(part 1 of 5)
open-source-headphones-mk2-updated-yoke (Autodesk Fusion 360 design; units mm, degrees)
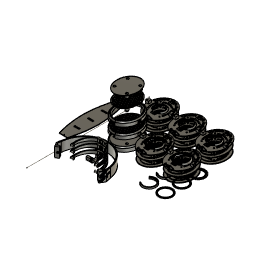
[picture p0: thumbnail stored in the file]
sketch "Pad Mount Start" plane through (0, 0, 0) normal (0, 0, 1) x axis (1, 0, 0)
  curve K1 (0, 53) -> (0, -53)
  curve K2 (-43, 0) -> (43, 0)
  curve K3 (0, 41) -> (0, -41)
  curve K4 (-31, 0) -> (31, 0)
  curve K5 (0, 43) -> (0, -43)
  curve K6 (-33, 0) -> (33, 0)
  line L1 (29.0688, 20.3542) -> (0, 0)
  line L2 (35.4865, 0) -> (0, 0)
  line L3 (20.8361, 33.3448) -> (0, 0)
  line L4 (39.3194, 0) -> (0, 0)
  curve K7 (0, -35.5) -> (0, 35.5)
  curve K8 (25.5, 0) -> (-25.5, 0)
  line L5 (29.0688, -20.3542) -> (0, 0)
  line L6 (20.8361, -33.3448) -> (0, 0)
  line L7 (0, 20) -> (0, 2.5)
  line L8 (-29.0688, -20.3542) -> (0, 0)
  line L9 (-20.8361, -33.3448) -> (0, 0)
  line L10 (-29.0688, 20.3542) -> (0, 0)
  line L11 (-20.8361, 33.3448) -> (0, 0)
  line L12 (37.023, 0) -> (0, 0)
  line L13 (11.725, -5.6147) -> (15.1969, -7.6193)
  line L14 (15.1969, 7.6193) -> (11.725, 5.6147)
  line L15 (1, 10.9545) -> (1, 6.9282)
  line L16 (6.5, -2.5981) -> (9.9868, -4.6112)
  line L17 (10.725, 7.3468) -> (14.1969, 9.3513)
  line L18 (1, 16.9706) -> (1, 12.9615)
  line L19 (11.43, 15.1775) -> (14.6475, 19.0119)
  line L20 (1, 23.9792) -> (1, 18.9737)
  line L21 (-1, 18.9737) -> (-1, 23.9792)
  line L22 (-14.6475, 19.0119) -> (-11.43, 15.1775)
  line L23 (-12.9621, 13.8919) -> (-16.1795, 17.7263)
  line L24 (-23.4412, 5.1487) -> (-18.5118, 4.2796)
  line L25 (-18.8591, 2.3099) -> (-23.7885, 3.1791)
  line L26 (-21.2666, -11.1236) -> (-16.9317, -8.6208)
  line L27 (-15.9317, -10.3529) -> (-20.2666, -12.8556)
  line L28 (-9.141, -22.191) -> (-7.4291, -17.4874)
  line L29 (-5.5497, -18.1714) -> (-7.2617, -22.8751)
  line L30 (7.2617, -22.8751) -> (5.5497, -18.1714)
  line L31 (7.4291, -17.4874) -> (9.141, -22.191)
  line L32 (20.2666, -12.8556) -> (15.9317, -10.3529)
  line L33 (16.9317, -8.6208) -> (21.2666, -11.1236)
  line L34 (23.7885, 3.1791) -> (18.8591, 2.3099)
  line L35 (18.5118, 4.2796) -> (23.4412, 5.1487)
  line L36 (16.1795, 17.7263) -> (12.9621, 13.8919)
  line L37 (-14.1969, 9.3513) -> (-10.725, 7.3468)
  line L38 (-1, 12.9615) -> (-1, 16.9706)
  line L39 (-11.725, 5.6147) -> (-15.1969, 7.6193)
  line L40 (-15.1969, -7.6193) -> (-11.725, -5.6147)
  line L41 (-9.9868, -4.6112) -> (-6.5, -2.5981)
  line L42 (-1, 6.9282) -> (-1, 10.9545)
  line L43 (8.9868, -6.3433) -> (5.5, -4.3301)
  line L44 (-5.5, -4.3301) -> (-8.9868, -6.3433)
  line L45 (-10.725, -7.3468) -> (-14.1969, -9.3513)
  line L46 (-1, -16.9706) -> (-1, -12.9615)
  line L47 (14.1969, -9.3513) -> (10.725, -7.3468)
  line L48 (1, -12.9615) -> (1, -16.9706)
  closed curve K9 centre (0, 0)
  closed curve K10 centre (0, 0)
  closed curve K11 centre (0, 0)
  circle C1 centre (0, 0) radius 24
  circle C2 centre (0, 0) radius 25.5
  circle C3 centre (0, 0) radius 29.5
  closed curve K12 centre (0, 0)
  arc A1 centre (0, 0) radius 17 clockwise from (15.1969, 7.6193) to (15.1969, -7.6193)
  arc A2 centre (0, 0) radius 13 clockwise from (11.725, 5.6147) to (11.725, -5.6147)
  arc A3 centre (0, 0) radius 7 clockwise from (1, 6.9282) to (6.5, -2.5981)
  arc A4 centre (0, 0) radius 11 clockwise from (1, 10.9545) to (9.9868, -4.6112)
  arc A5 centre (0, 0) radius 17 clockwise from (1, 16.9706) to (14.1969, 9.3513)
  arc A6 centre (0, 0) radius 13 clockwise from (1, 12.9615) to (10.725, 7.3468)
  arc A7 centre (0, 0) radius 24 clockwise from (14.6475, 19.0119) to (16.1795, 17.7263)
  arc A8 centre (0, 0) radius 19 clockwise from (1, 18.9737) to (11.43, 15.1775)
  arc A9 centre (0, 0) radius 24 clockwise from (-1, 23.9792) to (1, 23.9792)
  arc A10 centre (0, 0) radius 19 clockwise from (-11.43, 15.1775) to (-1, 18.9737)
  arc A11 centre (0, 0) radius 24 clockwise from (-16.1795, 17.7263) to (-14.6475, 19.0119)
  arc A12 centre (0, 0) radius 19 clockwise from (-18.5118, 4.2796) to (-12.9621, 13.8919)
  arc A13 centre (0, 0) radius 24 clockwise from (-23.7885, 3.1791) to (-23.4412, 5.1487)
  arc A14 centre (0, 0) radius 19 clockwise from (-16.9317, -8.6208) to (-18.8591, 2.3099)
  arc A15 centre (0, 0) radius 24 clockwise from (-20.2666, -12.8556) to (-21.2666, -11.1236)
  arc A16 centre (0, 0) radius 19 clockwise from (-7.4291, -17.4874) to (-15.9317, -10.3529)
  arc A17 centre (0, 0) radius 24 clockwise from (-7.2617, -22.8751) to (-9.141, -22.191)
  arc A18 centre (0, 0) radius 19 clockwise from (5.5497, -18.1714) to (-5.5497, -18.1714)
  arc A19 centre (0, 0) radius 24 clockwise from (9.141, -22.191) to (7.2617, -22.8751)
  arc A20 centre (0, 0) radius 19 clockwise from (15.9317, -10.3529) to (7.4291, -17.4874)
  arc A21 centre (0, 0) radius 24 clockwise from (21.2666, -11.1236) to (20.2666, -12.8556)
  arc A22 centre (0, 0) radius 19 clockwise from (18.8591, 2.3099) to (16.9317, -8.6208)
  arc A23 centre (0, 0) radius 24 clockwise from (23.4412, 5.1487) to (23.7885, 3.1791)
  arc A24 centre (0, 0) radius 19 clockwise from (12.9621, 13.8919) to (18.5118, 4.2796)
  arc A25 centre (0, 0) radius 13 clockwise from (-10.725, 7.3468) to (-1, 12.9615)
  arc A26 centre (0, 0) radius 17 clockwise from (-14.1969, 9.3513) to (-1, 16.9706)
  arc A27 centre (0, 0) radius 17 clockwise from (-15.1969, -7.6193) to (-15.1969, 7.6193)
  arc A28 centre (0, 0) radius 13 clockwise from (-11.725, -5.6147) to (-11.725, 5.6147)
  arc A29 centre (0, 0) radius 7 clockwise from (-6.5, -2.5981) to (-1, 6.9282)
  arc A30 centre (0, 0) radius 11 clockwise from (-9.9868, -4.6112) to (-1, 10.9545)
  arc A31 centre (0, 0) radius 7 clockwise from (5.5, -4.3301) to (-5.5, -4.3301)
  arc A32 centre (0, 0) radius 11 clockwise from (8.9868, -6.3433) to (-8.9868, -6.3433)
  arc A33 centre (0, 0) radius 17 clockwise from (-1, -16.9706) to (-14.1969, -9.3513)
  arc A34 centre (0, 0) radius 13 clockwise from (-1, -12.9615) to (-10.725, -7.3468)
  arc A35 centre (0, 0) radius 13 clockwise from (10.725, -7.3468) to (1, -12.9615)
  arc A36 centre (0, 0) radius 17 clockwise from (14.1969, -9.3513) to (1, -16.9706)
  circle C4 centre (0, 0) radius 5
  point P3 (0, -53)
  point P4 (0, 53)
  point P5 (43, 0)
  point P6 (-43, 0)
  point P1 (0, 0)
  point P2 (0, 0)
  point P8 (0, -41)
  point P9 (0, 41)
  point P10 (31, 0)
  point P11 (-31, 0)
  point P7 (0, 0)
  point P13 (0, -43)
  point P14 (0, 43)
  point P15 (33, 0)
  point P16 (-33, 0)
  point P17 (0, 0)
  point P20 (0, 0)
  point P21 (29.0688, 20.3542)
  point P23 (0, 0)
  point P24 (20.8361, 33.3448)
  point P27 (0, 35.5)
  point P28 (0, -35.5)
  point P29 (-25.5, 0)
  point P30 (25.5, 0)
  point P31 (0, 0)
  point P32 (29.0688, -20.3542)
  point P33 (0, 0)
  point P34 (20.8361, -33.3448)
  point P41 (0, 0)
  point P42 (-29.0688, 20.3542)
  point P43 (0, 0)
  point P44 (-20.8361, 33.3448)
  point P37 (0, 0)
  point P38 (-29.0688, -20.3542)
  point P39 (0, 0)
  point P40 (-20.8361, -33.3448)
  coincident K9 P3
  coincident K9 P4
  coincident K9 P5
  coincident K9 P6
  coincident P1 P2
  vertical K1
  coincident K10 P8
  coincident K10 P9
  coincident K10 P10
  coincident K10 P11
  coincident P1 P7
  perpendicular K2 K3
  coincident K11 P13
  coincident K11 P14
  coincident K11 P15
  coincident K11 P16
  concentric K9 K11
  perpendicular K4 K5
  concentric K11 C1
  concentric K9 C2
  concentric K9 C3
  horizontal L2
  coincident P17 P20
  coincident K11 P21
  horizontal L4
  coincident P7 P23
  coincident K11 P24
  coincident K12 P27
  coincident K12 P28
  coincident K12 P29
  coincident K12 P30
  concentric K10 K12
  parallel K3 K7
  symmetric P20 L2 P31
  symmetric P21 L2 P32
  symmetric L2 P23 P33
  symmetric L2 P24 P34
  symmetric P20 L7 P41
  symmetric P21 L7 P42
  symmetric P23 L7 P43
  symmetric P24 L7 P44
  symmetric P31 L7 P37
  symmetric P32 L7 P38
  symmetric P33 L7 P39
  symmetric P34 L7 P40
  horizontal L12
  dimension "d1" distance K9 = 106
  dimension "d2" = 86
  dimension "d3" distance K10 = 82
  dimension "d4" = 62
  dimension "d5" distance K11 = 86
  dimension "d6" = 66
  dimension "d7" diameter C1 = 48
  dimension "d8" diameter C2 = 51
  dimension "d9" diameter C3 = 59
  dimension "d10" angle L1 L2 = 35
  dimension "d11" angle L3 L4 = 58
  dimension "d12" distance K12 = 71
  dimension "d13" = 51
  dimension "d660" angle P16 = 20
extrude "Extrude1" new body sketch "Pad Mount Start" profile of K9 K11 along normal blind 2
extrude "Extrude2" add sketch "Pad Mount Start" profile of K10 K11 C2 C3 along normal blind 5
extrude "Extrude3" add sketch "Pad Mount Start" profile of C1 C2 A7 A9 A11 A13 A15 A17 A19 A21 A23 along normal blind 2.5
extrude "Extrude4" add sketch "Pad Mount Start" profile of C1 A1 L13 L14 A2 L15 A3 L16 A4 A5 L17 L18 A6 A7 L19 A8 L20 A9 L21 A10 L22 A11 L23 A12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 along normal blind 1.5
component_from_bodies "Body->Comp1"
sketch "Sketch2" plane through (0, 0, 5) normal (0, 0, 1) x axis (-1, 0, 0)
  line L1 (-20.8361, -33.3448) -> (0, 0)
  line L2 (-29.0688, -20.3542) -> (0, 0)
  line L3 (-29.0688, 20.3542) -> (0, 0)
  line L4 (-20.8361, 33.3448) -> (0, 0)
  line L5 (20.8361, 33.3448) -> (0, 0)
  line L6 (29.0688, 20.3542) -> (0, 0)
  line L7 (29.0688, -20.3542) -> (0, 0)
  line L8 (20.8361, -33.3448) -> (0, 0)
  curve K1 (0, 41) -> (0, -41)
  curve K2 (-31, 0) -> (31, 0)
  curve K3 (-27, 0) -> (27, 0)
  curve K4 (0, -37) -> (0, 37)
  circle C1 centre (0, 0) radius 25.5
  closed curve K5 centre (0, 0)
  closed curve K6 centre (0, 0)
  closed curve K7 centre (0, 0)
  circle C2 centre (0, 0) radius 29.5
  circle C3 centre (0, 0) radius 33.5
  point P20 (0, -41)
  point P21 (0, 41)
  point P22 (31, 0)
  point P23 (-31, 0)
  point P15 (0, 0)
  point P16 (0, 0)
  point P25 (27, 0)
  point P26 (-27, 0)
  point P27 (0, 37)
  point P28 (0, -37)
  point P4 (0, 0)
  point P24 (0, 0)
  point P9 (0, 0)
  point P29 (0, 0)
  coincident K6 P20
  coincident K6 P21
  coincident K6 P22
  coincident K6 P23
  coincident P15 P16
  coincident K7 P25
  coincident K7 P26
  coincident K7 P27
  coincident K7 P28
  coincident P4 P24
  parallel K2 K3
  coincident P9 P29
  concentric K6 C3
  dimension "d37" distance K6 = 82
  dimension "d38" = 62
  dimension "d41" distance K7 = 54
  dimension "d42" = 74
  dimension "d43" diameter C2 = 59
  dimension "d44" diameter C3 = 67
extrude "Extrude2" cut sketch "Sketch2" profile of L1 L2 L3 L4 L5 L6 L7 L8 K6 K7 C2 C3 against normal blind 5
sketch "Sketch3" plane through (0, 0, 0) normal (0, 0, -1) x axis (1, 0, 0)
  line L1 (17.7523, -28.4096) -> (15.6326, -25.0174)
  line L2 (-15.6326, -25.0174) -> (-17.7523, -28.4096)
  line L3 (-27.3973, -19.1838) -> (-24.0432, -16.8352)
  line L4 (-24.0432, 16.8352) -> (-27.3973, 19.1838)
  line L5 (-17.7523, 28.4096) -> (-15.6326, 25.0174)
  line L6 (15.6326, 25.0174) -> (17.7523, 28.4096)
  line L7 (27.3973, 19.1838) -> (24.0432, 16.8352)
  line L8 (24.0432, -16.8352) -> (27.3973, -19.1838)
  line L9 (12.9621, -13.8919) -> (16.1795, -17.7263)
  line L10 (23.4412, -5.1487) -> (18.5118, -4.2796)
  line L11 (18.8591, -2.3099) -> (23.7885, -3.1791)
  line L12 (21.2666, 11.1236) -> (16.9317, 8.6208)
  line L13 (15.9317, 10.3529) -> (20.2666, 12.8556)
  line L14 (9.141, 22.191) -> (7.4291, 17.4874)
  line L15 (5.5497, 18.1714) -> (7.2617, 22.8751)
  line L16 (-7.2617, 22.8751) -> (-5.5497, 18.1714)
  line L17 (-7.4291, 17.4874) -> (-9.141, 22.191)
  line L18 (-20.2666, 12.8556) -> (-15.9317, 10.3529)
  line L19 (-16.9317, 8.6208) -> (-21.2666, 11.1236)
  line L20 (-23.7885, -3.1791) -> (-18.8591, -2.3099)
  line L21 (-18.5118, -4.2796) -> (-23.4412, -5.1487)
  line L22 (-16.1795, -17.7263) -> (-12.9621, -13.8919)
  line L23 (-11.43, -15.1775) -> (-14.6475, -19.0119)
  line L24 (-1, -23.9792) -> (-1, -18.9737)
  line L25 (-1, -10.9545) -> (-1, -6.9282)
  line L26 (-6.5, 2.5981) -> (-9.9868, 4.6112)
  line L27 (-1, 12.9615) -> (-1, 16.9706)
  line L28 (-14.1969, 9.3513) -> (-10.725, 7.3468)
  line L29 (1, -12.9615) -> (1, -16.9706)
  line L30 (14.1969, -9.3513) -> (10.725, -7.3468)
  line L31 (11.725, -5.6147) -> (15.1969, -7.6193)
  line L32 (15.1969, 7.6193) -> (11.725, 5.6147)
  line L33 (-11.725, 5.6147) -> (-15.1969, 7.6193)
  line L34 (-15.1969, -7.6193) -> (-11.725, -5.6147)
  line L35 (-1, -16.9706) -> (-1, -12.9615)
  line L36 (-10.725, -7.3468) -> (-14.1969, -9.3513)
  line L37 (-8.9868, 6.3433) -> (-5.5, 4.3301)
  line L38 (5.5, 4.3301) -> (8.9868, 6.3433)
  line L39 (1, 16.9706) -> (1, 12.9615)
  line L40 (10.725, 7.3468) -> (14.1969, 9.3513)
  line L41 (9.9868, 4.6112) -> (6.5, 2.5981)
  line L42 (1, -6.9282) -> (1, -10.9545)
  line L43 (1, -18.9737) -> (1, -23.9792)
  line L44 (14.6475, -19.0119) -> (11.43, -15.1775)
  line L45 (22.8469, -24.5003) -> (0, 0)
  line L46 (33.5, 0) -> (0, 0)
  line L47 (-22.8469, -24.5003) -> (0, 0)
  line L48 (-33.5, 0) -> (0, 0)
  line L49 (-22.8469, 24.5003) -> (0, 0)
  line L50 (22.8469, 24.5003) -> (0, 0)
  arc A1 centre (0, 0) radius 33.5 clockwise from (17.7523, -28.4096) to (-17.7523, -28.4096)
  arc A2 centre (0, 0) radius 29.5 clockwise from (15.6326, -25.0174) to (-15.6326, -25.0174)
  closed curve K1 centre (0, 0)
  closed curve K2 centre (0, 0)
  arc A3 centre (0, 0) radius 33.5 clockwise from (-17.7523, 28.4096) to (17.7523, 28.4096)
  arc A4 centre (0, 0) radius 29.5 clockwise from (-15.6326, 25.0174) to (15.6326, 25.0174)
  closed curve K3 centre (0, 0)
  closed curve K4 centre (0, 0)
  arc A5 centre (0, 0) radius 24 clockwise from (23.4412, -5.1487) to (16.1795, -17.7263)
  arc A6 centre (0, 0) radius 19 clockwise from (18.5118, -4.2796) to (12.9621, -13.8919)
  arc A7 centre (0, 0) radius 19 clockwise from (16.9317, 8.6208) to (18.8591, -2.3099)
  arc A8 centre (0, 0) radius 24 clockwise from (21.2666, 11.1236) to (23.7885, -3.1791)
  arc A9 centre (0, 0) radius 19 clockwise from (7.4291, 17.4874) to (15.9317, 10.3529)
  arc A10 centre (0, 0) radius 24 clockwise from (9.141, 22.191) to (20.2666, 12.8556)
  arc A11 centre (0, 0) radius 19 clockwise from (-5.5497, 18.1714) to (5.5497, 18.1714)
  arc A12 centre (0, 0) radius 24 clockwise from (-7.2617, 22.8751) to (7.2617, 22.8751)
  arc A13 centre (0, 0) radius 19 clockwise from (-15.9317, 10.3529) to (-7.4291, 17.4874)
  arc A14 centre (0, 0) radius 24 clockwise from (-20.2666, 12.8556) to (-9.141, 22.191)
  arc A15 centre (0, 0) radius 19 clockwise from (-18.8591, -2.3099) to (-16.9317, 8.6208)
  arc A16 centre (0, 0) radius 24 clockwise from (-23.7885, -3.1791) to (-21.2666, 11.1236)
  arc A17 centre (0, 0) radius 19 clockwise from (-12.9621, -13.8919) to (-18.5118, -4.2796)
  arc A18 centre (0, 0) radius 24 clockwise from (-16.1795, -17.7263) to (-23.4412, -5.1487)
  arc A19 centre (0, 0) radius 19 clockwise from (-1, -18.9737) to (-11.43, -15.1775)
  arc A20 centre (0, 0) radius 24 clockwise from (-1, -23.9792) to (-14.6475, -19.0119)
  arc A21 centre (0, 0) radius 11 clockwise from (-1, -10.9545) to (-9.9868, 4.6112)
  arc A22 centre (0, 0) radius 7 clockwise from (-1, -6.9282) to (-6.5, 2.5981)
  arc A23 centre (0, 0) radius 17 clockwise from (-14.1969, 9.3513) to (-1, 16.9706)
  arc A24 centre (0, 0) radius 13 clockwise from (-10.725, 7.3468) to (-1, 12.9615)
  arc A25 centre (0, 0) radius 17 clockwise from (14.1969, -9.3513) to (1, -16.9706)
  arc A26 centre (0, 0) radius 13 clockwise from (10.725, -7.3468) to (1, -12.9615)
  arc A27 centre (0, 0) radius 17 clockwise from (15.1969, 7.6193) to (15.1969, -7.6193)
  arc A28 centre (0, 0) radius 13 clockwise from (11.725, 5.6147) to (11.725, -5.6147)
  arc A29 centre (0, 0) radius 17 clockwise from (-15.1969, -7.6193) to (-15.1969, 7.6193)
  arc A30 centre (0, 0) radius 13 clockwise from (-11.725, -5.6147) to (-11.725, 5.6147)
  arc A31 centre (0, 0) radius 17 clockwise from (-1, -16.9706) to (-14.1969, -9.3513)
  arc A32 centre (0, 0) radius 13 clockwise from (-1, -12.9615) to (-10.725, -7.3468)
  arc A33 centre (0, 0) radius 11 clockwise from (-8.9868, 6.3433) to (8.9868, 6.3433)
  arc A34 centre (0, 0) radius 7 clockwise from (-5.5, 4.3301) to (5.5, 4.3301)
  circle C1 centre (0, 0) radius 5
  arc A35 centre (0, 0) radius 17 clockwise from (1, 16.9706) to (14.1969, 9.3513)
  arc A36 centre (0, 0) radius 13 clockwise from (1, 12.9615) to (10.725, 7.3468)
  arc A37 centre (0, 0) radius 11 clockwise from (9.9868, 4.6112) to (1, -10.9545)
  arc A38 centre (0, 0) radius 7 clockwise from (6.5, 2.5981) to (1, -6.9282)
  arc A39 centre (0, 0) radius 19 clockwise from (11.43, -15.1775) to (1, -18.9737)
  arc A40 centre (0, 0) radius 24 clockwise from (14.6475, -19.0119) to (1, -23.9792)
  closed curve K5 centre (0, 0)
  circle C2 centre (0, 0) radius 33.5
  circle C3 centre (-22.8469, -24.5003) radius 2.2
  circle C4 centre (-22.8469, -24.5003) radius 4
  circle C5 centre (-22.8469, -24.5003) radius 4.5
  circle C6 centre (22.8469, -24.5003) radius 2.2
  circle C7 centre (22.8469, -24.5003) radius 4
  circle C8 centre (22.8469, -24.5003) radius 4.5
  circle C9 centre (-22.8469, 24.5003) radius 4.5
  circle C10 centre (-22.8469, 24.5003) radius 4
  circle C11 centre (-22.8469, 24.5003) radius 2.2
  circle C12 centre (22.8469, 24.5003) radius 4.5
  circle C13 centre (22.8469, 24.5003) radius 4
  circle C14 centre (22.8469, 24.5003) radius 2.2
  point P1 (0, 0)
  point P92 (0, 0)
  point P93 (22.8469, -24.5003)
  point P5 (0, 0)
  point P95 (0, 0)
  point P96 (-22.8469, -24.5003)
  point P100 (0, 0)
  point P101 (22.8469, 24.5003)
  point P98 (0, 0)
  point P99 (-22.8469, 24.5003)
  point P102 (-22.8469, -24.5003)
  point P103 (-22.8469, -24.5003)
  point P104 (-22.8469, -24.5003)
  point P105 (22.8469, -24.5003)
  concentric A1 C2
  horizontal L46
  coincident P1 P92
  coincident C2 P93
  horizontal L48
  coincident P5 P95
  coincident C2 P96
  symmetric P92 L46 P100
  symmetric P93 L46 P101
  symmetric L46 P95 P98
  symmetric L46 P96 P99
  coincident P96 P102
  coincident P96 P103
  coincident P96 P104
  coincident P93 P105
  concentric C6 C7
  concentric C6 C8
  symmetric L48 C3 C11
  symmetric L48 C4 C10
  symmetric L48 C5 C9
  symmetric L48 C6 C14
  symmetric L48 C7 C13
  symmetric L48 C8 C12
  dimension "d59" diameter C2 = 67
  dimension "d60" angle L45 L46 = 47
  dimension "d61" angle L47 L48 = 47
  dimension "d62" diameter C3 = 4.4
  dimension "d63" diameter C4 = 8
  dimension "d64" diameter C5 = 9
  dimension "d65" diameter C6 = 4.4
  dimension "d66" diameter C7 = 8
  dimension "d67" diameter C8 = 9
extrude "Extrude5" cut sketch "Sketch3" profile of C3 C6 C11 C14 against normal blind 5
extrude "Extrude6" cut sketch "Sketch3" profile of C3 C4 C6 C7 C10 C11 C13 C14 against normal blind 3
sketch "Sketch4" plane through (0, 0, 5) normal (0, 0, 1) x axis (-1, 0, 0)
  line L1 (-15.6326, -25.0174) -> (-17.7523, -28.4096)
  line L2 (17.7523, -28.4096) -> (15.6326, -25.0174)
  line L3 (24.0432, -16.8352) -> (27.3973, -19.1838)
  line L4 (27.3973, 19.1838) -> (24.0432, 16.8352)
  line L5 (15.6326, 25.0174) -> (17.7523, 28.4096)
  line L6 (-17.7523, 28.4096) -> (-15.6326, 25.0174)
  line L7 (-24.0432, 16.8352) -> (-27.3973, 19.1838)
  line L8 (-27.3973, -19.1838) -> (-24.0432, -16.8352)
  circle C1 centre (22.8469, -24.5003) radius 2.2
  circle C2 centre (22.8469, 24.5003) radius 2.2
  circle C3 centre (-22.8469, -24.5003) radius 2.2
  circle C4 centre (-22.8469, 24.5003) radius 2.2
  arc A1 centre (0, 0) radius 29.5 clockwise from (15.6326, -25.0174) to (-15.6326, -25.0174)
  arc A2 centre (0, 0) radius 33.5 clockwise from (17.7523, -28.4096) to (-17.7523, -28.4096)
  closed curve K1 centre (0, 0)
  closed curve K2 centre (0, 0)
  arc A3 centre (0, 0) radius 29.5 clockwise from (-15.6326, 25.0174) to (15.6326, 25.0174)
  arc A4 centre (0, 0) radius 33.5 clockwise from (-17.7523, 28.4096) to (17.7523, 28.4096)
  closed curve K3 centre (0, 0)
  closed curve K4 centre (0, 0)
  circle C5 centre (0, 0) radius 25.5
  closed curve K5 centre (0, 0)
  circle C6 centre (22.8469, -24.5003) radius 4.5
  circle C7 centre (-22.8469, -24.5003) radius 4.5
  circle C8 centre (22.8469, 24.5003) radius 4.5
  circle C9 centre (-22.8469, 24.5003) radius 4.5
  concentric C1 C6
  concentric C3 C7
  concentric C2 C8
  concentric C4 C9
  dimension "d72" diameter C6 = 9
  dimension "d73" diameter C7 = 9
  dimension "d74" diameter C8 = 9
  dimension "d75" diameter C9 = 9
extrude "Extrude7" add sketch "Sketch4" profile of K5 C6 C7 C8 C9 against normal blind 3
extrude "Extrude8" cut of existing geometry blind -1
work_plane "WorkPlane1" AlongDistance 20
sketch "Driver Clamp" plane through (0, 0, 20) normal (0, 0, 1) x axis (1, 0, 0)
  curve K1 (0, 55) -> (0, -55)
  curve K2 (-45, 0) -> (45, 0)
  line L1 (29.0688, -20.3542) -> (0, 0)
  line L2 (20.8361, -33.3448) -> (0, 0)
  line L3 (-20.8361, -33.3448) -> (0, 0)
  line L4 (-29.0688, -20.3542) -> (0, 0)
  line L5 (-29.0688, 20.3542) -> (0, 0)
  line L6 (-20.8361, 33.3448) -> (0, 0)
  curve K3 (0, 41) -> (0, -41)
  curve K4 (-31, 0) -> (31, 0)
  curve K5 (-27, 0) -> (27, 0)
  curve K6 (0, -37) -> (0, 37)
  line L7 (20.8361, 33.3448) -> (0, 0)
  line L8 (29.0688, 20.3542) -> (0, 0)
  closed curve K7 centre (0, 0)
  circle C1 centre (22.8469, -24.5003) radius 2.2
  circle C2 centre (-22.8469, -24.5003) radius 2.2
  circle C3 centre (-22.8469, 24.5003) radius 2.2
  circle C4 centre (22.8469, 24.5003) radius 2.2
  circle C5 centre (0, 0) radius 25.2
  circle C6 centre (0, 0) radius 27.5
  circle C7 centre (0, 0) radius 29.5
  circle C8 centre (0, 0) radius 33.5
  closed curve K8 centre (0, 0)
  closed curve K9 centre (0, 0)
  point P3 (0, -55)
  point P4 (0, 55)
  point P5 (45, 0)
  point P6 (-45, 0)
  point P1 (0, 0)
  point P2 (0, 0)
  point P11 (0, 0)
  point P12 (0, 0)
  point P29 (0, -41)
  point P30 (0, 41)
  point P31 (31, 0)
  point P32 (-31, 0)
  point P33 (27, 0)
  point P34 (-27, 0)
  point P35 (0, 37)
  point P36 (0, -37)
  point P13 (0, 0)
  point P15 (0, 0)
  point P25 (0, 0)
  point P28 (0, 0)
  coincident K7 P3
  coincident K7 P4
  coincident K7 P5
  coincident K7 P6
  coincident P1 P2
  vertical K1
  coincident P1 P11
  coincident P1 P12
  coincident K8 P29
  coincident K8 P30
  coincident K8 P31
  coincident K8 P32
  coincident K9 P33
  coincident K9 P34
  coincident K9 P35
  coincident K9 P36
  coincident P13 P15
  parallel K4 K5
  coincident P25 P28
  concentric C8 K8
  dimension "d81" distance K7 = 110
  dimension "d82" = 90
  dimension "d83" diameter C5 = 50.4
  dimension "d84" diameter C6 = 55
  dimension "d85" distance K8 = 82
  dimension "d86" = 62
  dimension "d87" distance K9 = 54
  dimension "d88" = 74
  dimension "d89" diameter C7 = 59
  dimension "d90" diameter C8 = 67
extrude "Extrude9" new body sketch "Driver Clamp" profile of K7 C1 C2 C3 C4 C5 C6 L1 L2 L3 L4 L5 L6 C7 C8 K8 K9 L7 L8 along normal blind 2
sketch "Sketch6" plane through (0, 0, 22) normal (0, 0, 1) x axis (-1, 0, 0)
  line L1 (-24.0432, 16.8352) -> (-27.3973, 19.1838)
  line L2 (-27.3973, -19.1838) -> (-24.0432, -16.8352)
  line L3 (-17.7523, 28.4096) -> (-15.6326, 25.0174)
  line L4 (15.6326, 25.0174) -> (17.7523, 28.4096)
  line L5 (-15.6326, -25.0174) -> (-17.7523, -28.4096)
  line L6 (17.7523, -28.4096) -> (15.6326, -25.0174)
  line L7 (27.3973, 19.1838) -> (24.0432, 16.8352)
  line L8 (24.0432, -16.8352) -> (27.3973, -19.1838)
  line L9 (8, 35.5) -> (-8, 35.5)
  line L10 (8, 23.5) -> (8, 35.5)
  line L11 (-8, 23.5) -> (8, 23.5)
  line L12 (-8, 35.5) -> (-8, 23.5)
  line L13 (8, 23.5) -> (-8, 35.5)
  line L14 (-8, 23.5) -> (8, 35.5)
  closed curve K1 centre (0, 0)
  arc A1 centre (0, 0) radius 27.5 clockwise from (-26.4189, -7.6348) to (-26.4189, 7.6348)
  closed curve K2 centre (0, 0)
  closed curve K3 centre (0, 0)
  arc A2 centre (0, 0) radius 29.5 clockwise from (-15.6326, 25.0174) to (15.6326, 25.0174)
  arc A3 centre (0, 0) radius 33.5 clockwise from (-17.7523, 28.4096) to (17.7523, 28.4096)
  circle C1 centre (-22.8469, -24.5003) radius 2.2
  circle C2 centre (-22.8469, 24.5003) radius 2.2
  circle C3 centre (22.8469, -24.5003) radius 2.2
  circle C4 centre (0, 0) radius 25.2
  circle C5 centre (22.8469, 24.5003) radius 2.2
  arc A4 centre (0, 0) radius 29.5 clockwise from (15.6326, -25.0174) to (-15.6326, -25.0174)
  arc A5 centre (0, 0) radius 33.5 clockwise from (17.7523, -28.4096) to (-17.7523, -28.4096)
  closed curve K4 centre (0, 0)
  closed curve K5 centre (0, 0)
  closed curve K6 centre (0, 0)
  arc A6 centre (0, 0) radius 27.5 clockwise from (26.4189, 7.6348) to (26.4189, -7.6348)
  closed curve K7 centre (0, 0)
  point P31 (0, 29.5)
  point P29 (8, 23.5)
  point P30 (-8, 23.5)
  point P28 (8, 35.5)
  horizontal L9
  perpendicular L9 L10
  parallel L9 L11
  parallel L10 L12
  coincident L13 P31
  coincident L14 P31
  midpoint A2 P31
  dimension "d93" distance P29 P30 = 16
  dimension "d94" distance P28 P29 = 12
extrude "Extrude10" cut sketch "Sketch6" profile of A2 C4 L10 L12 against normal blind 2
extrude "Extrude11" add sketch "Sketch6" profile of A2 L3 A3 L4 L10 L12 against normal blind 2
sketch "Sketch7" plane through (0, 0, 22) normal (0, 0, 1) x axis (-1, 0, 0)
  line L1 (27.3973, 19.1838) -> (24.0432, 16.8352)
  line L2 (24.0432, -16.8352) -> (27.3973, -19.1838)
  line L3 (-15.6326, -25.0174) -> (-17.7523, -28.4096)
  line L4 (17.7523, -28.4096) -> (15.6326, -25.0174)
  line L5 (-8, 32.5308) -> (-8, 23.8964)
  line L6 (8, 23.8964) -> (8, 32.5308)
  line L7 (-24.0432, 16.8352) -> (-27.3973, 19.1838)
  line L8 (-27.3973, -19.1838) -> (-24.0432, -16.8352)
  line L9 (25.2, 0) -> (0, 0)
  line L10 (-25.2, 0) -> (0, 0)
  line L11 (19.4454, 19.4454) -> (0, 0)
  line L12 (27.5, 0) -> (0, 0)
  line L13 (-19.4454, 19.4454) -> (0, 0)
  line L14 (-27.5, 0) -> (0, 0)
  closed curve K1 centre (0, 0)
  closed curve K2 centre (0, 0)
  closed curve K3 centre (0, 0)
  closed curve K4 centre (0, 0)
  arc A1 centre (0, 0) radius 27.5 clockwise from (26.4189, 7.6348) to (26.4189, -7.6348)
  arc A2 centre (0, 0) radius 29.5 clockwise from (15.6326, -25.0174) to (-15.6326, -25.0174)
  arc A3 centre (0, 0) radius 33.5 clockwise from (17.7523, -28.4096) to (-17.7523, -28.4096)
  circle C1 centre (22.8469, 24.5003) radius 2.2
  circle C2 centre (22.8469, -24.5003) radius 2.2
  circle C3 centre (-22.8469, 24.5003) radius 2.2
  circle C4 centre (-22.8469, -24.5003) radius 2.2
  arc A4 centre (0, 0) radius 33.5 clockwise from (-8, 32.5308) to (8, 32.5308)
  arc A5 centre (0, 0) radius 25.2 clockwise from (8, 23.8964) to (-8, 23.8964)
  closed curve K5 centre (0, 0)
  arc A6 centre (0, 0) radius 27.5 clockwise from (-26.4189, -7.6348) to (-26.4189, 7.6348)
  closed curve K6 centre (0, 0)
  closed curve K7 centre (0, 0)
  circle C5 centre (0, 0) radius 21
  circle C6 centre (0, 0) radius 25.2
  circle C7 centre (0, 0) radius 27.5
  point P1 (0, 0)
  point P27 (0, 0)
  point P20 (8, 23.8964)
  point P2 (0, 0)
  point P29 (0, 0)
  point P31 (0, 0)
  point P34 (0, 0)
  point P35 (19.4454, 19.4454)
  point P37 (-19.4454, 19.4454)
  coincident P1 P27
  concentric K1 C6
  coincident P20 C6
  horizontal L9
  coincident P2 P29
  horizontal L10
  coincident P2 P31
  concentric K1 C7
  horizontal L12
  coincident P2 P34
  coincident C7 P35
  horizontal L14
  coincident C7 P37
  dimension "d99" diameter C5 = 42
  dimension "d102" diameter C7 = 55
  dimension "d103" angle L11 L12 = 45
  dimension "d104" angle L13 L14 = 45
extrude "Extrude12" add sketch "Sketch7" profile of A1 A5 A6 C5 C6 C7 L11 L13 along normal blind 4
chamfer "Chamfer1" distance 4.2 Rotate Angle 40
chamfer "Chamfer2" distance 4 Rotate Angle 45
sketch "Sketch8" plane through (0, 0, 22) normal (0, 0, 1) x axis (-1, 0, 0)
  line L1 (-27.3973, -19.1838) -> (-24.0432, -16.8352)
  line L2 (-24.0432, 16.8352) -> (-27.3973, 19.1838)
  line L3 (-17.8191, 17.8191) -> (-19.4454, 19.4454)
  line L4 (-8, 32.5308) -> (-8, 23.8964)
  line L5 (8, 23.8964) -> (8, 32.5308)
  line L6 (19.4454, 19.4454) -> (17.8191, 17.8191)
  line L7 (27.3973, 19.1838) -> (24.0432, 16.8352)
  line L8 (24.0432, -16.8352) -> (27.3973, -19.1838)
  line L9 (-15.6326, -25.0174) -> (-17.7523, -28.4096)
  line L10 (17.7523, -28.4096) -> (15.6326, -25.0174)
  curve K1 (0, 52.8) -> (0, -52.8)
  curve K2 (-42.8, 0) -> (42.8, 0)
  curve K3 (0, 50.8) -> (0, -50.8)
  curve K4 (-40.8, 0) -> (40.8, 0)
  line L11 (-8, 32.5308) -> (8, 32.5308)
  line L12 (-8, 55.0308) -> (-8, 32.5308)
  line L13 (8, 55.0308) -> (-8, 55.0308)
  line L14 (8, 32.5308) -> (8, 55.0308)
  line L15 (-6, 53.0308) -> (-6, 32.5308)
  line L16 (6, 53.0308) -> (-6, 53.0308)
  line L17 (6, 32.5308) -> (6, 53.0308)
  line L18 (17.2573, 46.032) -> (8, 49.8139)
  line L19 (18.1032, 47.8443) -> (17.2573, 46.032)
  line L20 (-17.2573, 46.032) -> (-8, 49.8139)
  line L21 (-18.1032, 47.8443) -> (-17.2573, 46.032)
  line L22 (6, 55.0308) -> (6, 53.0308)
  line L23 (-6, 55.0308) -> (-6, 53.0308)
  line L24 (-8, 54.1239) -> (-6, 55.0308)
  line L25 (8, 54.1239) -> (6, 55.0308)
  arc A1 centre (0, 0) radius 27.5 clockwise from (26.4189, -7.6348) to (-26.4189, -7.6348)
  closed curve K5 centre (0, 0)
  closed curve K6 centre (0, 0)
  closed curve K7 centre (0, 0)
  arc A2 centre (0, 0) radius 27.5 clockwise from (-26.4189, 7.6348) to (-19.4454, 19.4454)
  arc A3 centre (0, 0) radius 25.2 clockwise from (-17.8191, 17.8191) to (-8, 23.8964)
  arc A4 centre (0, 0) radius 33.5 clockwise from (-8, 32.5308) to (8, 32.5308)
  arc A5 centre (0, 0) radius 25.2 clockwise from (8, 23.8964) to (17.8191, 17.8191)
  arc A6 centre (0, 0) radius 27.5 clockwise from (19.4454, 19.4454) to (26.4189, 7.6348)
  closed curve K8 centre (0, 0)
  closed curve K9 centre (0, 0)
  closed curve K10 centre (0, 0)
  closed curve K11 centre (0, 0)
  arc A7 centre (0, 0) radius 29.5 clockwise from (15.6326, -25.0174) to (-15.6326, -25.0174)
  arc A8 centre (0, 0) radius 33.5 clockwise from (17.7523, -28.4096) to (-17.7523, -28.4096)
  circle C1 centre (22.8469, 24.5003) radius 2.2
  circle C2 centre (22.8469, -24.5003) radius 2.2
  circle C3 centre (-22.8469, 24.5003) radius 2.2
  circle C4 centre (-22.8469, -24.5003) radius 2.2
  closed curve K12 centre (0, 0)
  closed curve K13 centre (0, 0)
  point P32 (0, -52.8)
  point P33 (0, 52.8)
  point P34 (42.8, 0)
  point P35 (-42.8, 0)
  point P1 (0, 0)
  point P31 (0, 0)
  point P37 (0, -50.8)
  point P38 (0, 50.8)
  point P39 (40.8, 0)
  point P40 (-40.8, 0)
  point P14 (8, 32.5308)
  point P41 (8, 32.5308)
  point P49 (8, 49.8139)
  point P50 (17.2573, 46.032)
  point P51 (18.1032, 47.8443)
  point P52 (-8, 49.8139)
  point P53 (-17.2573, 46.032)
  point P54 (-18.1032, 47.8443)
  point P55 (6, 55.0308)
  point P56 (-6, 55.0308)
  point P57 (-8, 54.1239)
  point P58 (8, 54.1239)
  point P42 (-8, 32.5308)
  point P44 (8, 55.0308)
  coincident K12 P32
  coincident K12 P33
  coincident K12 P34
  coincident K12 P35
  coincident P1 P31
  vertical K1
  coincident K13 P37
  coincident K13 P38
  coincident K13 P39
  coincident K13 P40
  concentric A1 K13
  perpendicular K2 K3
  horizontal L11
  vertical L12
  horizontal L13
  vertical L14
  coincident P14 P41
  coincident L14 P49
  coincident K13 P49
  coincident K13 P50
  coincident K12 P51
  coincident K13 P52
  coincident L12 P52
  coincident K13 P53
  coincident K12 P54
  coincident L13 P55
  perpendicular L13 L22
  coincident L13 P56
  perpendicular L13 L23
  coincident L12 P57
  coincident K11 P57
  coincident L14 P58
  coincident K11 P58
  dimension "d111" distance K12 = 105.6
  dimension "d112" = 85.6
  dimension "d113" distance K13 = 101.6
  dimension "d114" = 81.6
  dimension "d115" distance P41 P42 = 16
  dimension "d116" distance P41 P44 = 22.5
  dimension "d117" = 2
  dimension "d118" distance P49 P50 = 10
  dimension "d119" distance P50 P51 = 2
  dimension "d120" distance P52 P53 = 10
  dimension "d121" distance P53 P54 = 2
extrude "Extrude13" add sketch "Sketch8" profile of K11 L13 L24 L25 against normal blind 2
extrude "Extrude14" add sketch "Sketch8" profile of K11 K12 K13 L12 L13 L14 L15 L17 L16 L19 L21 L24 L25 along normal blind 10.2
sketch "3.5mm Socket" plane through (0, -53.0308, 0) normal (0, 1, 0) x axis (-1, 0, 0)
  line L1 (6, 22) -> (-6, 22)
  line L2 (6, 32.2) -> (6, 22)
  line L3 (-6, 32.2) -> (6, 32.2)
  line L4 (-6, 22) -> (-6, 32.2)
  circle C1 centre (0, 27.1) radius 3.15
  dimension "d126" diameter C1 = 6.3
extrude "Extrude15" cut sketch "3.5mm Socket" profile of C1 against normal blind 2
chamfer "Chamfer3" distance 10.2 Rotate Angle 45
sketch "Sketch23" plane through (0, 0, 22) normal (0, 0, 1) x axis (-1, 0, 0)
  line L1 (-8, 54.1239) -> (-8, 51.8694)
  line L2 (8, 51.8694) -> (8, 54.1239)
  line L3 (17.2573, 46.032) -> (18.1032, 47.8443)
  line L4 (6, 53.0308) -> (6, 50.2477)
  line L5 (-6, 53.0308) -> (6, 53.0308)
  line L6 (-6, 50.2477) -> (-6, 53.0308)
  line L7 (-18.1032, 47.8443) -> (-17.2573, 46.032)
  line L8 (-27.3973, -19.1838) -> (-24.0432, -16.8352)
  line L9 (-24.0432, 16.8352) -> (-27.3973, 19.1838)
  line L10 (-17.8191, 17.8191) -> (-19.4454, 19.4454)
  line L11 (-8, 32.5308) -> (-8, 23.8964)
  line L12 (8, 23.8964) -> (8, 32.5308)
  line L13 (19.4454, 19.4454) -> (17.8191, 17.8191)
  line L14 (27.3973, 19.1838) -> (24.0432, 16.8352)
  line L15 (24.0432, -16.8352) -> (27.3973, -19.1838)
  line L16 (-15.6326, -25.0174) -> (-17.7523, -28.4096)
  line L17 (17.7523, -28.4096) -> (15.6326, -25.0174)
  closed curve K1 centre (0, 0)
  closed curve K2 centre (0, 0)
  closed curve K3 centre (0, 0)
  closed curve K4 centre (0, 0)
  closed curve K5 centre (0, 0)
  arc A1 centre (0, 0) radius 27.5 clockwise from (26.4189, -7.6348) to (-26.4189, -7.6348)
  closed curve K6 centre (0, 0)
  closed curve K7 centre (0, 0)
  closed curve K8 centre (0, 0)
  arc A2 centre (0, 0) radius 27.5 clockwise from (-26.4189, 7.6348) to (-19.4454, 19.4454)
  arc A3 centre (0, 0) radius 25.2 clockwise from (-17.8191, 17.8191) to (-8, 23.8964)
  arc A4 centre (0, 0) radius 33.5 clockwise from (-8, 32.5308) to (8, 32.5308)
  arc A5 centre (0, 0) radius 25.2 clockwise from (8, 23.8964) to (17.8191, 17.8191)
  arc A6 centre (0, 0) radius 27.5 clockwise from (19.4454, 19.4454) to (26.4189, 7.6348)
  closed curve K9 centre (0, 0)
  closed curve K10 centre (0, 0)
  closed curve K11 centre (0, 0)
  arc A7 centre (0, 0) radius 29.5 clockwise from (15.6326, -25.0174) to (-15.6326, -25.0174)
  arc A8 centre (0, 0) radius 33.5 clockwise from (17.7523, -28.4096) to (-17.7523, -28.4096)
  circle C1 centre (22.8469, 24.5003) radius 2.2
  circle C2 centre (22.8469, -24.5003) radius 2.2
  circle C3 centre (-22.8469, 24.5003) radius 2.2
  circle C4 centre (-22.8469, -24.5003) radius 2.2
  closed curve K12 centre (0, 0)
  dimension "d698" Text1-Height = 8
extrude "Extrude43" add sketch "Sketch23" along normal blind 0.5
work_plane "WorkPlane2" AlongDistance 58
sketch "Shell" plane through (0, 0, 58) normal (0, 0, 1) x axis (1, 0, 0)
  curve K1 (0, -55) -> (0, 55)
  curve K2 (45, 0) -> (-45, 0)
  curve K3 (0, -53) -> (0, 53)
  curve K4 (43, 0) -> (-43, 0)
  line L1 (-8.2, -51) -> (8.2, -51)
  line L2 (-8.2, -55) -> (-8.2, -51)
  line L3 (8.2, -55) -> (-8.2, -55)
  line L4 (8.2, -51) -> (8.2, -55)
  line L5 (-8.2, -55) -> (8.2, -51)
  line L6 (8.2, -55) -> (-8.2, -51)
  curve K5 (0, -50.6) -> (0, 50.6)
  curve K6 (40.6, 0) -> (-40.6, 0)
  line L7 (-18.3979, -47.9039) -> (-8.2, -52.0274)
  line L8 (-17.371, -45.7346) -> (-18.3979, -47.9039)
  line L9 (18.3979, -47.9039) -> (8.2, -52.0274)
  line L10 (17.371, -45.7346) -> (18.3979, -47.9039)
  curve K7 (0, -48.6) -> (0, 48.6)
  curve K8 (38.6, 0) -> (-38.6, 0)
  line L11 (-16.5153, -43.9269) -> (-17.371, -45.7346)
  line L12 (-19.2536, -49.7115) -> (-18.3979, -47.9039)
  line L13 (19.2536, -49.7115) -> (18.3979, -47.9039)
  line L14 (16.5153, -43.9269) -> (17.371, -45.7346)
  line L15 (-22.8469, -20.228) -> (-19.1469, -22.3642)
  line L16 (-26.5469, -22.3642) -> (-22.8469, -20.228)
  line L17 (-26.5469, -26.6365) -> (-26.5469, -22.3642)
  line L18 (-22.8469, -28.7727) -> (-26.5469, -26.6365)
  line L19 (-19.1469, -26.6365) -> (-22.8469, -28.7727)
  line L20 (-19.1469, -22.3642) -> (-19.1469, -26.6365)
  line L21 (22.8469, -20.228) -> (26.5469, -22.3642)
  line L22 (19.1469, -22.3642) -> (22.8469, -20.228)
  line L23 (19.1469, -26.6365) -> (19.1469, -22.3642)
  line L24 (22.8469, -28.7727) -> (19.1469, -26.6365)
  line L25 (26.5469, -26.6365) -> (22.8469, -28.7727)
  line L26 (26.5469, -22.3642) -> (26.5469, -26.6365)
  line L27 (-22.8469, 28.7727) -> (-19.1469, 26.6365)
  line L28 (-26.5469, 26.6365) -> (-22.8469, 28.7727)
  line L29 (-26.5469, 22.3642) -> (-26.5469, 26.6365)
  line L30 (-22.8469, 20.228) -> (-26.5469, 22.3642)
  line L31 (-19.1469, 22.3642) -> (-22.8469, 20.228)
  line L32 (-19.1469, 26.6365) -> (-19.1469, 22.3642)
  line L33 (22.8469, 28.7727) -> (26.5469, 26.6365)
  line L34 (19.1469, 26.6365) -> (22.8469, 28.7727)
  line L35 (19.1469, 22.3642) -> (19.1469, 26.6365)
  line L36 (22.8469, 20.228) -> (19.1469, 22.3642)
  line L37 (26.5469, 22.3642) -> (22.8469, 20.228)
  line L38 (26.5469, 26.6365) -> (26.5469, 22.3642)
  line L39 (-8.2, -47.4907) -> (-8.2, -51)
  line L40 (8.2, -47.4907) -> (8.2, -51)
  closed curve K9 centre (0, 0)
  closed curve K10 centre (0, 0)
  closed curve K11 centre (0, 0)
  closed curve K12 centre (0, 0)
  circle C1 centre (22.8469, 24.5003) radius 2.2
  circle C2 centre (-22.8469, 24.5003) radius 2.2
  circle C3 centre (-22.8469, -24.5003) radius 2.2
  circle C4 centre (22.8469, -24.5003) radius 2.2
  circle C5 centre (22.8469, 24.5003) radius 6
  circle C6 centre (-22.8469, 24.5003) radius 6
  circle C7 centre (-22.8469, -24.5003) radius 6
  circle C8 centre (22.8469, -24.5003) radius 6
  point P3 (0, 55)
  point P4 (0, -55)
  point P5 (-45, 0)
  point P6 (45, 0)
  point P1 (0, 0)
  point P2 (0, 0)
  point P8 (0, 53)
  point P9 (0, -53)
  point P10 (-43, 0)
  point P11 (43, 0)
  point P16 (0, -53)
  point P18 (0, 50.6)
  point P19 (0, -50.6)
  point P20 (-40.6, 0)
  point P21 (40.6, 0)
  point P17 (0, 0)
  point P22 (-8.2, -52.0274)
  point P23 (-18.3979, -47.9039)
  point P24 (-17.371, -45.7346)
  point P25 (8.2, -52.0274)
  point P26 (18.3979, -47.9039)
  point P27 (17.371, -45.7346)
  point P29 (0, 48.6)
  point P30 (0, -48.6)
  point P31 (-38.6, 0)
  point P32 (38.6, 0)
  point P33 (-16.5153, -43.9269)
  point P34 (-19.2536, -49.7115)
  point P35 (19.2536, -49.7115)
  point P36 (16.5153, -43.9269)
  point P39 (-22.8469, -24.5003)
  point P47 (-22.8469, -24.5003)
  point P37 (22.8469, -24.5003)
  point P54 (22.8469, -24.5003)
  point P38 (-22.8469, 24.5003)
  point P61 (-22.8469, 24.5003)
  point P40 (22.8469, 24.5003)
  point P68 (22.8469, 24.5003)
  point P69 (22.8469, 24.5003)
  point P70 (-22.8469, 24.5003)
  point P73 (-8.2, -47.4907)
  point P14 (-8.2, -55)
  point P15 (8.2, -55)
  point P13 (-8.2, -51)
  coincident K9 P3
  coincident K9 P4
  coincident K9 P5
  coincident K9 P6
  coincident P1 P2
  vertical K1
  coincident K10 P8
  coincident K10 P9
  coincident K10 P10
  coincident K10 P11
  concentric K9 K10
  perpendicular K2 K3
  horizontal L1
  perpendicular L1 L2
  parallel L1 L3
  parallel L2 L4
  coincident L5 P16
  coincident L6 P16
  coincident P9 P16
  coincident K11 P18
  coincident K11 P19
  coincident K11 P20
  coincident K11 P21
  coincident P1 P17
  perpendicular K2 K5
  coincident K10 P22
  coincident L2 P22
  coincident K10 P23
  coincident K11 P24
  coincident L4 P25
  coincident K10 P25
  coincident K10 P26
  coincident K11 P27
  coincident K12 P29
  coincident K12 P30
  coincident K12 P31
  coincident K12 P32
  concentric K11 K12
  parallel K1 K7
  coincident K12 P33
  parallel L8 L11
  coincident K9 P34
  parallel L8 L12
  parallel L10 L13
  coincident K9 P35
  coincident K12 P36
  parallel L10 L14
  coincident P39 P47
  coincident P37 P54
  coincident P38 P61
  coincident P40 P68
  coincident P68 P69
  coincident P61 P70
  concentric C3 C7
  concentric C4 C8
  coincident K12 P73
  perpendicular L1 L39
  perpendicular L1 L40
  dimension "d132" distance K9 = 110
  dimension "d133" = 90
  dimension "d134" distance K10 = 106
  dimension "d135" = 86
  dimension "d136" distance P14 P15 = 16.4
  dimension "d137" distance P13 P14 = 4
  dimension "d138" distance K11 = 101.2
  dimension "d139" = 81.2
  dimension "d140" distance P22 P23 = 11
  dimension "d141" distance P23 P24 = 2.4
  dimension "d142" distance P25 P26 = 11
  dimension "d143" distance P26 P27 = 2.4
  dimension "d144" distance K12 = 97.2
  dimension "d145" = 77.2
  dimension "d147" distance P47 L20 = 3.7
  dimension "d148" distance P54 L26 = 3.7
  dimension "d149" distance P61 L32 = 3.7
  dimension "d150" distance P68 L38 = 3.7
  dimension "d151" diameter C5 = 12
  dimension "d152" diameter C6 = 12
  dimension "d153" diameter C7 = 12
  dimension "d154" diameter C8 = 12
extrude "Extrude16" new body sketch "Shell" profile of K9 K10 L2 L4 K11 L8 L10 K12 L11 L12 L13 L14 L39 L40 against normal blind 16 bodies "Closed Shell"
extrude "Extrude17" add sketch "Shell" profile of K9 K10 L2 L4 K11 K12 L39 L40 against normal blind 5.8
copy_paste_bodies "CopyPasteBodies1"
move "Move1"
combine "Combine1" bodies "Driver Clamp (1)"
offset_faces "OffsetFaces1" distance -0.2
extrude "Extrude19" add sketch "Shell" profile of K10 K11 L8 L10 K12 L11 L14 C5 C6 C7 C8 L39 L40 against normal blind 4
extrude "Extrude20" add sketch "Shell" profile of C1 C2 C3 C4 L15 L16 L17 L18 L19 L20 L21 L22 L23 L24 L25 L26 L27 L28 L29 L30 L31 L32 L33 L34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 against normal blind 16
extrude "Extrude21" cut sketch "Shell" profile of C1 C2 C3 C4 L15 L16 L17 L18 L19 L20 L21 L22 L23 L24 L25 L26 L27 L28 L29 L30 L31 L32 L33 L34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 against normal blind 11.5
chamfer "Chamfer5" distance 1.8 distance 4
chamfer "Chamfer6" distance 2 distance 1.8
chamfer "Chamfer7" distance 4
sketch "Sketch16" plane through (0, 0, 42) normal (0, 0, -1) x axis (1, 0, 0)
  line L1 (-18.4338, 47.8837) -> (-18.4335, 47.8831)
  curve K1 (-18.4338, 47.8837) -> (-8.2, 52.0276)
  line L2 (-8.2, 54.0792) -> (-8.2, 52.0276)
  line L3 (8.2, 52.0276) -> (8.2, 54.0792)
  curve K2 (8.2, 52.0276) -> (18.4338, 47.8837)
  line L4 (18.4335, 47.8831) -> (18.4338, 47.8837)
  line L5 (-45, -5.7) -> (45, -5.7)
  line L6 (-45, 5.7) -> (-45, -5.7)
  line L7 (45, 5.7) -> (-45, 5.7)
  line L8 (45, -5.7) -> (45, 5.7)
  line L9 (-45, 5.7) -> (45, -5.7)
  line L10 (45, 5.7) -> (-45, -5.7)
  closed curve K3 centre (0, 0)
  closed curve K4 centre (0, 0)
  point P15 (0, 0)
  point P1 (0, 0)
  point P13 (-45, 5.7)
  point P14 (45, 5.7)
  point P12 (-45, -5.7)
  horizontal L5
  perpendicular L5 L6
  parallel L5 L7
  parallel L6 L8
  coincident L9 P15
  coincident L10 P15
  coincident P1 P15
  dimension "d547" distance P13 P14 = 90
  dimension "d548" distance P12 P13 = 11.4
extrude "Extrude30" cut sketch "Sketch16" profile of K3 K4 L5 L7 against normal blind 9.1
chamfer "Chamfer9" distance 1.73 Rotate Angle 50
copy_paste_bodies "CopyPasteBodies2"
move "Move2"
